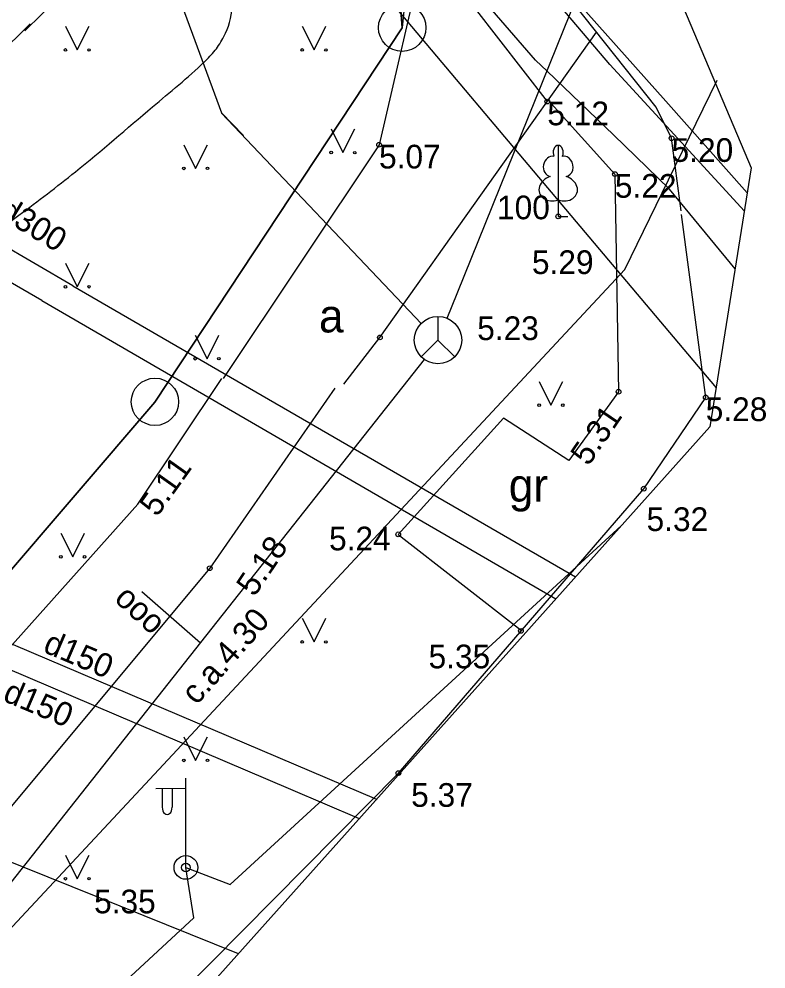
# Model space of a CAD drawing. Extents: x 519536 to 519949, y 326041 to 326519.
# Drawn here: x 519868.77 to 519884.54, y 326160.59 to 326180.65 of the extents above; entities that cross this region are included whole.
import ezdxf

# ---------------------------------------------------------------- set-up
doc = ezdxf.new("R2010")
doc.units = 0
for name, color, linetype in [('APGR_ELEM_####_####_#', 7, 'Continuous'), ('APGR_SARK_####_####_#', 7, 'Continuous'), ('APGS_ELEM_####_####_#', 7, 'Continuous'), ('APGS_VADP_ZSPR_####_#', 7, 'Continuous'), ('CELI_CMAL_####_####_#', 7, 'Continuous'), ('CELI_CSEG_####_TKST_#', 7, 'Continuous'), ('CELI_SEGL_####_####_#', 7, 'Continuous'), ('ELEK_VADP_ZSPR_####_#', 7, 'Continuous'), ('GAZE_VADP_VSP2_####_#', 7, 'Continuous'), ('RAMI_UZMR_####_####_#', 7, 'Continuous'), ('RELJ_AATZ_####_TKST_#', 7, 'Continuous'), ('RELJ_ELEM_####_####_#', 7, 'Continuous'), ('RELJ_HORZ_PAMT_####_#', 7, 'Continuous'), ('ROBZ_PROJ_####_####_#', 7, 'Continuous'), ('ROBZ_UZMR_####_####_#', 7, 'Continuous'), ('SAKK_ELEM_####_####_#', 7, 'Continuous'), ('SAKK_ELEM_####_TKST_#', 7, 'Continuous'), ('SAKK_IZVK_####_TKST_#', 7, 'Continuous'), ('SAKK_KKAN_####_####_#', 7, 'Continuous'), ('SAKK_KKAN_####_TKST_#', 7, 'Continuous'), ('SAKT_VADP_NEDR_####_#', 7, 'Continuous'), ('SILT_VADP_NEDR_####_#', 7, 'Continuous'), ('SILT_VADP_NEDR_TKST_#', 7, 'Continuous'), ('SKAN_VADP_PAST_####_#', 7, 'Continuous'), ('SKAN_VADP_SPDK_####_#', 7, 'Continuous'), ('SKAN_VADP_SPDK_TKST_#', 7, 'Continuous'), ('TERT_DIAM_####_TKST_#', 7, 'Continuous'), ('TERT_ELEM_####_####_#', 7, 'Continuous'), ('UDTK_VADP_UDEN_####_#', 7, 'Continuous')]:
    doc.layers.add(name, color=color, linetype=linetype)

msp = doc.modelspace()

# ---------------------------------------------------------------- linework, layer by layer
at = {"layer": 'APGR_ELEM_####_####_#'}
for centre in [(519876.86, 326180.47), (519871.64, 326172.57)]:
    msp.add_circle(centre, 0.5, dxfattribs=at)
at = {"layer": 'APGR_SARK_####_####_#'}
for p, q in [((519877.92, 326191.345), (519876.86, 326180.47)), ((519876.86, 326180.47), (519871.637, 326172.566)), ((519871.637, 326172.566), (519860.475, 326159.533))]:
    msp.add_line(p, q, dxfattribs=at)
at = {"layer": 'APGS_ELEM_####_####_#'}
for p, q in [((519872.294, 326162.737), (519872.294, 326164.62)), ((519872.294, 326164.404), (519871.659, 326164.399)), ((519871.794, 326164.4), (519871.794, 326164.008)), ((519872.004, 326164.402), (519872.004, 326164.008))]:
    msp.add_line(p, q, dxfattribs=at)
for radius in [0.25, 0.09]:
    msp.add_circle((519872.294, 326162.737), radius, dxfattribs=at)
msp.add_ellipse((519871.899, 326164.008), major_axis=(0, 0.151), ratio=0.695971, start_param=1.570796, end_param=4.712389, dxfattribs=at)
at = {"layer": 'APGS_VADP_ZSPR_####_#'}
msp.add_lwpolyline([(519855.101, 326145.579), (519860.112, 326150.242), (519872.459, 326161.672), (519872.294, 326162.737), (519873.229, 326162.379), (519881.483, 326169.953)], dxfattribs=at)
at = {"layer": 'CELI_CMAL_####_####_#'}
for points in [[(519882.222, 326178.789), (519878.977, 326182.88), (519874.995, 326188.433), (519867.888, 326197.765), (519858.139, 326210.779), (519849.58, 326222.15), (519841.494, 326233.418), (519836.895, 326239.916), (519835.264, 326243.212)], [(519877.351, 326182.225), (519876.372, 326177.998), (519873.083, 326173.06)], [(519875.627, 326172.944), (519876.391, 326173.93), (519880.964, 326180.376)], [(519879.944, 326178.937), (519881.35, 326177.38), (519881.428, 326172.783), (519880.377, 326171.328), (519879.001, 326172.228), (519876.777, 326169.772), (519879.376, 326167.739)], [(519882.749, 326176.606), (519882.547, 326178.137), (519882.222, 326178.789)], [(519855.978, 326144.717), (519858.12, 326146.642), (519869.551, 326157.415), (519876.782, 326164.73), (519881.96, 326170.736), (519883.268, 326172.663), (519882.76, 326176.524)], [(519850.188, 326148.028), (519862.033, 326160.062), (519871.277, 326170.41), (519873.051, 326173.065)], [(519875.436, 326172.858), (519872.797, 326169.056), (519863.845, 326158.315), (519853.117, 326147.531)]]:
    msp.add_lwpolyline(points, dxfattribs=at)
at = {"layer": 'CELI_SEGL_####_####_#'}
msp.add_lwpolyline([(519877.351, 326182.225), (519879.924, 326178.91)], dxfattribs=at)
at = {"layer": 'ELEK_VADP_ZSPR_####_#'}
for points in [[(519872.559, 326188.693), (519875.181, 326187.3), (519879.283, 326182.454), (519882.424, 326178.919)], [(519882.13, 326178.73), (519881.246, 326179.694), (519874.989, 326187.062), (519872.629, 326188.316)], [(519872.258, 326186.198), (519879.625, 326177.451)], [(519882.424, 326178.919), (519884.145, 326176.982)], [(519884.083, 326176.599), (519882.13, 326178.73)], [(519879.625, 326177.451), (519883.485, 326172.867)]]:
    msp.add_lwpolyline(points, dxfattribs=at)
at = {"layer": 'GAZE_VADP_VSP2_####_#'}
msp.add_line((519881.32, 326178.21), (519882.502, 326177.059), dxfattribs=at)
for points in [[(519881.32, 326178.21), (519879.918, 326179.555), (519879.676, 326179.787), (519875.839, 326184.216), (519876.124, 326184.544)], [(519883.888, 326175.379), (519882.502, 326177.059)]]:
    msp.add_lwpolyline(points, dxfattribs=at)
at = {"layer": 'RAMI_UZMR_####_####_#'}
msp.add_lwpolyline([(519873.021, 326209.453), (519881.37, 326184.273), (519884.229, 326177.508), (519883.353, 326172.044), (519868.284, 326155.201), (519831.787, 326123.789), (519817.117, 326113.183), (519808.359, 326108.08), (519804.649, 326107.204), (519795.685, 326122.565), (519782.956, 326146.875), (519761.4, 326134.85), (519741.243, 326123.664), (519728.435, 326146.148), (519720.513, 326144.604), (519669.064, 326119.018)], dxfattribs=at)
at = {"layer": 'RELJ_ELEM_####_####_#'}
for centre in [(519879.924, 326178.91), (519882.547, 326178.137), (519876.372, 326177.998), (519881.35, 326177.38), (519880.154, 326176.486), (519876.391, 326173.93), (519881.428, 326172.783), (519883.268, 326172.663), (519881.96, 326170.736), (519876.777, 326169.772), (519872.797, 326169.056), (519879.367, 326167.734), (519876.782, 326164.73)]:
    msp.add_circle(centre, 0.05, dxfattribs=at)
at = {"layer": 'RELJ_HORZ_PAMT_####_#'}
for points in [[(519868.771, 326176.513), (519869.962, 326177.426), (519871.589, 326178.798), (519872.684, 326179.748), (519872.912, 326179.993), (519873.009, 326180.132), (519873.098, 326180.283), (519873.275, 326180.902), (519873.243, 326182.152), (519873.235, 326183.496), (519873.315, 326184.23), (519873.486, 326184.949), (519873.717, 326185.66), (519873.976, 326186.366)], [(519864.5, 326173.942), (519864.521, 326173.956), (519864.813, 326174.034), (519865.716, 326174.535), (519868.306, 326176.185), (519868.771, 326176.513)]]:
    msp.add_spline(points, degree=3, dxfattribs=at)
at = {"layer": 'ROBZ_PROJ_####_####_#'}
for p, q in [((519876.86, 326180.47), (519876.321, 326187.374)), ((519871.637, 326172.566), (519876.86, 326180.47)), ((519860.475, 326159.533), (519871.637, 326172.566))]:
    msp.add_line(p, q, dxfattribs=at)
at = {"layer": 'ROBZ_UZMR_####_####_#'}
for p, q in [((519876.321, 326187.374), (519876.86, 326180.47)), ((519876.86, 326180.47), (519871.637, 326172.566)), ((519871.637, 326172.566), (519860.475, 326159.533))]:
    msp.add_line(p, q, dxfattribs=at)
at = {"layer": 'SAKK_ELEM_####_####_#'}
msp.add_line((519877.616, 326173.874), (519877.97, 326173.52), dxfattribs=at)
msp.add_lwpolyline([(519877.616, 326174.374), (519877.616, 326173.874), (519877.262, 326173.52)], dxfattribs=at)
msp.add_circle((519877.616, 326173.874), 0.5, dxfattribs=at)
at = {"layer": 'SAKK_IZVK_####_TKST_#'}
msp.add_line((519872.601, 326167.477), (519871.367, 326168.555), dxfattribs=at)
at = {"layer": 'SAKK_KKAN_####_####_#'}
for points in [[(519869.677, 326187.826), (519873.048, 326178.67), (519873.513, 326178.196)], [(519880.279, 326180.451), (519881.601, 326183.726)], [(519878.022, 326174.856), (519880.279, 326180.451)], [(519877.135, 326174.357), (519873.047, 326178.669)], [(519877.811, 326174.334), (519878.022, 326174.856)], [(519877.26, 326174.225), (519877.135, 326174.357)], [(519862.677, 326154.937), (519865.566, 326158.57), (519868.474, 326162.251), (519877.329, 326173.464)]]:
    msp.add_lwpolyline(points, dxfattribs=at)
at = {"layer": 'SAKT_VADP_NEDR_####_#'}
for points in [[(519882.485, 326177.26), (519883.508, 326179.364)], [(519862.229, 326154.715), (519866.7, 326159.421), (519881.563, 326175.364), (519882.485, 326177.26)]]:
    msp.add_lwpolyline(points, dxfattribs=at)
at = {"layer": 'SILT_VADP_NEDR_####_#'}
for p, q in [((519869.909, 326175.02), (519864.201, 326178.331)), ((519869.253, 326174.707), (519864.213, 326177.631))]:
    msp.add_line(p, q, dxfattribs=at)
for points in [[(519869.909, 326175.02), (519873.371, 326173.013)], [(519869.253, 326174.707), (519872.323, 326172.926)], [(519873.371, 326173.013), (519880.516, 326168.872)], [(519872.323, 326172.926), (519880.103, 326168.412)]]:
    msp.add_lwpolyline(points, dxfattribs=at)
at = {"layer": 'SKAN_VADP_PAST_####_#'}
msp.add_lwpolyline([(519863.363, 326164.961), (519873.401, 326160.92)], dxfattribs=at)
at = {"layer": 'SKAN_VADP_SPDK_####_#'}
for points in [[(519865.896, 326168.615), (519876.317, 326164.179)], [(519865.696, 326168.146), (519874.502, 326164.389), (519875.951, 326163.77)]]:
    msp.add_lwpolyline(points, dxfattribs=at)
at = {"layer": 'TERT_ELEM_####_####_#'}
for p, q in [((519869.75, 326180.5), (519870, 326180)), ((519870, 326180), (519870.25, 326180.5)), ((519874.75, 326180.5), (519875, 326180)), ((519875, 326180), (519875.25, 326180.5)), ((519875.359, 326178.333), (519875.609, 326177.833)), ((519875.609, 326177.833), (519875.859, 326178.333)), ((519872.25, 326178), (519872.5, 326177.5)), ((519872.5, 326177.5), (519872.75, 326178)), ((519880.154, 326176.833), (519880.154, 326176.486)), ((519880.154, 326176.486), (519880.354, 326176.486)), ((519869.75, 326175.5), (519870, 326175)), ((519870, 326175), (519870.25, 326175.5)), ((519872.49, 326173.981), (519872.74, 326173.481)), ((519872.74, 326173.481), (519872.99, 326173.981)), ((519879.75, 326172.999), (519880, 326172.499)), ((519880, 326172.499), (519880.25, 326172.999)), ((519869.655, 326169.798), (519869.905, 326169.298)), ((519869.905, 326169.298), (519870.155, 326169.798)), ((519874.749, 326167.999), (519874.999, 326167.499)), ((519874.999, 326167.499), (519875.249, 326167.999)), ((519872.25, 326165.499), (519872.5, 326164.999)), ((519872.5, 326164.999), (519872.75, 326165.499)), ((519869.75, 326163), (519870, 326162.5)), ((519870, 326162.5), (519870.25, 326163))]:
    msp.add_line(p, q, dxfattribs=at)
for points in [[(519880.154, 326177.986), (519880.154, 326176.833)], [(519880.244, 326177.754), (519880.243, 326177.755)]]:
    msp.add_lwpolyline(points, dxfattribs=at)
for centre, radius in [((519869.75, 326180), 0.028), ((519870.25, 326180), 0.0263), ((519874.75, 326180), 0.028), ((519875.25, 326180), 0.0263), ((519875.359, 326177.833), 0.028), ((519875.859, 326177.833), 0.0263), ((519872.25, 326177.5), 0.028), ((519872.75, 326177.5), 0.0263), ((519869.75, 326175), 0.028), ((519870.25, 326175), 0.0263), ((519872.49, 326173.481), 0.028), ((519872.99, 326173.481), 0.0263), ((519879.75, 326172.499), 0.028), ((519880.25, 326172.499), 0.0263), ((519869.655, 326169.298), 0.028), ((519870.155, 326169.298), 0.0263), ((519874.749, 326167.499), 0.028), ((519875.249, 326167.499), 0.0263), ((519872.25, 326164.999), 0.028), ((519872.75, 326164.999), 0.0263), ((519869.75, 326162.5), 0.028), ((519870.25, 326162.5), 0.0263)]:
    msp.add_circle(centre, radius, dxfattribs=at)
for centre, major_axis, ratio, start_param, end_param in [((519880.154, 326177.836), (0, -0.15), 0.707107, 3.14537, 5.287485), ((519880.154, 326177.836), (0, -0.15), 0.707107, 0.995701, 3.137816), ((519880.026, 326177.541), (-0.039, -0.212), 0.861323, 3.141593, 6.283185), ((519880.282, 326177.541), (0.039, -0.212), 0.861323, 0, 3.141593), ((519880.064, 326177.079), (0.307, 0.095), 0.814445, 1.570796, 4.752015), ((519880.244, 326177.079), (-0.307, 0.095), 0.814445, 1.531171, 4.712389)]:
    msp.add_ellipse(centre, major_axis=major_axis, ratio=ratio, start_param=start_param, end_param=end_param, dxfattribs=at)
at = {"layer": 'UDTK_VADP_UDEN_####_#'}
for p, q in [((519868.894, 326180.401), (519872.896, 326184.362)), ((519858.637, 326170.382), (519869.008, 326180.55))]:
    msp.add_line(p, q, dxfattribs=at)

# ---------------------------------------------------------------- texts
at = {"layer": 'CELI_CSEG_####_TKST_#'}
for s, p in [('a', (519875.103, 326174.036)), ('gr', (519879.11, 326170.46))]:
    msp.add_text(s, height=0.7, dxfattribs=at).set_placement(p)
at = {"layer": 'RELJ_AATZ_####_TKST_#'}
for s, p in [('5.12', (519879.924, 326178.41)), ('5.07', (519876.372, 326177.498)), ('5.20', (519882.547, 326177.637)), ('5.22', (519881.35, 326176.88)), ('5.29', (519879.599, 326175.269)), ('5.28', (519883.268, 326172.163)), ('5.32', (519882.019, 326169.842)), ('5.24', (519875.316, 326169.434)), ('5.35', (519877.417, 326166.943)), ('5.37', (519877.05, 326164.018)), ('5.35', (519870.356, 326161.769))]:
    msp.add_text(s, height=0.5, dxfattribs=at).set_placement(p)
for s, rotation, p in [('5.31', 55.7602, (519880.792, 326171.195)), ('5.11', 54.5924, (519871.685, 326170.12)), ('5.18', 56.072, (519873.74, 326168.433))]:
    msp.add_text(s, height=0.5, rotation=rotation, dxfattribs=at).set_placement(p)
at = {"layer": 'SAKK_ELEM_####_TKST_#'}
msp.add_text('5.23', height=0.5, dxfattribs=at).set_placement((519878.444, 326173.874))
at = {"layer": 'SAKK_IZVK_####_TKST_#'}
msp.add_text('ooo', height=0.5, rotation=137.5351, dxfattribs=at).set_placement((519871.842, 326167.911))
at = {"layer": 'SAKK_KKAN_####_TKST_#'}
msp.add_text('c.a.4.30', height=0.5, rotation=48.751, dxfattribs=at).set_placement((519872.523, 326166.15))
at = {"layer": 'SILT_VADP_NEDR_TKST_#'}
msp.add_text('2xd300', height=0.5, rotation=328.6865, dxfattribs=at).set_placement((519867.705, 326176.856))
at = {"layer": 'SKAN_VADP_SPDK_TKST_#'}
for p in [(519869.254, 326167.299), (519868.405, 326166.268)]:
    msp.add_text('d150', height=0.5, rotation=336.89, dxfattribs=at).set_placement(p)
at = {"layer": 'TERT_DIAM_####_TKST_#'}
msp.add_text('100', height=0.5, dxfattribs=at).set_placement((519878.862, 326176.425))

doc.saveas('drawing.dxf')
